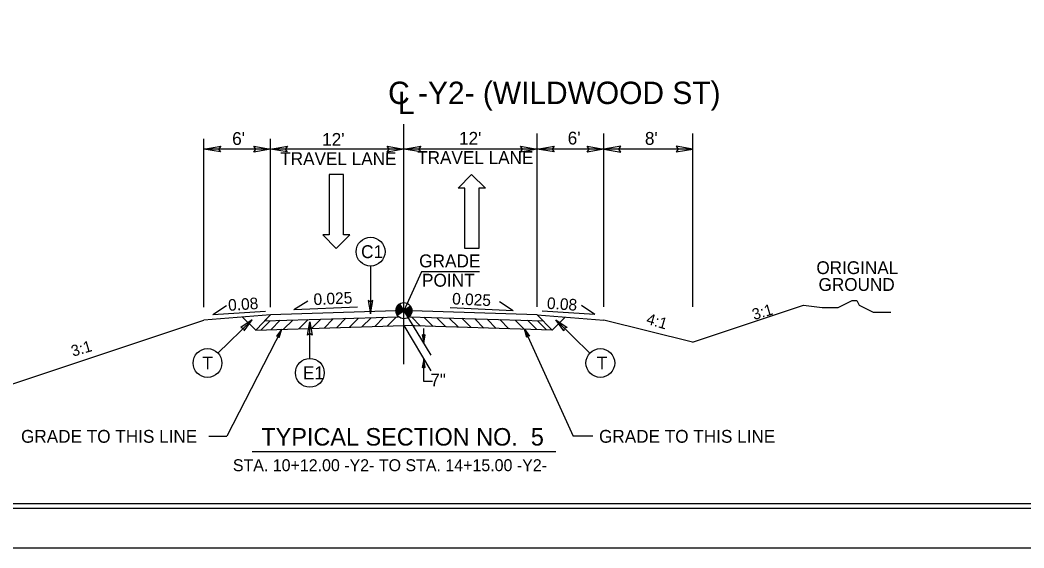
# Model space of a CAD drawing. Extents: x 2176156 to 2177167, y 76401 to 76644.
# Drawn here: x 2176675.5 to 2176765.8, y 76454.5 to 76502 of the extents above; entities that cross this region are included whole.
import ezdxf

# ---------------------------------------------------------------- set-up
doc = ezdxf.new("R2010")
doc.units = 0
for name, color, linetype in [('Exist Building', 7, 'Continuous'), ('Exist Building Metal Canopy', 7, 'Continuous'), ('Exist Roads Change in Surface', 7, 'Continuous'), ('Exist Roads Curbs', 7, 'Continuous'), ('Exist Roads EOP Other', 7, 'Continuous'), ('Exist Roads Soil', 7, 'Continuous'), ('Exist Structure Minor Culvert Topo', 7, 'Continuous'), ('Exist Structure Minor Drop Inlet', 7, 'Continuous'), ('Exist Utilities Other Pole CELL', 7, 'Continuous'), ('Exist Vegetation Woods Line', 7, 'Continuous'), ('Model Boundary Lines Text', 7, 'Continuous'), ('Old_Level_1', 7, 'Continuous'), ('Old_Level_3', 7, 'Continuous'), ('Prop North Arrow NAD83 for Plan Sheets CELL', 7, 'Continuous'), ('Sheet Cutting Line CELL', 7, 'Continuous'), ('Sheet Data Field CELL', 7, 'Continuous'), ('Sheet Plot Border Outside CELL', 7, 'Continuous'), ('Sheet Sticker Exception Certification CELL', 7, 'Continuous')]:
    doc.layers.add(name, color=color, linetype=linetype)

msp = doc.modelspace()

# ---------------------------------------------------------------- linework, layer by layer
at = {"layer": 'Exist Building'}
for p, q in [((2176696.696, 76474.077), (2176695.524, 76475.25)), ((2176723.371, 76474.077), (2176724.544, 76475.25)), ((2176696.696, 76474.077), (2176710.034, 76474.493)), ((2176723.371, 76474.077), (2176710.034, 76474.493))]:
    msp.add_line(p, q, dxfattribs=at)
at = {"layer": 'Exist Roads Change in Surface'}
for p, q in [((2176709.622, 76476.417), (2176710.034, 76475.825)), ((2176709.441, 76475.415), (2176710.034, 76475.825)), ((2176710.034, 76475.825), (2176709.441, 76475.415)), ((2176710.034, 76475.825), (2176710.625, 76476.237)), ((2176710.445, 76475.233), (2176710.034, 76475.825))]:
    msp.add_line(p, q, dxfattribs=at)
for points in [[(2176709.665, 76476.355), (2176709.401, 76476.171)], [(2176709.657, 76476.367), (2176709.417, 76476.2)], [(2176709.648, 76476.379), (2176709.437, 76476.231)], [(2176709.64, 76476.39), (2176709.464, 76476.268)], [(2176709.632, 76476.402), (2176709.498, 76476.309)], [(2176709.624, 76476.414), (2176709.559, 76476.369)], [(2176709.788, 76476.177), (2176709.313, 76475.846)], [(2176709.797, 76476.166), (2176709.313, 76475.829)], [(2176709.805, 76476.154), (2176709.313, 76475.812)], [(2176709.78, 76476.189), (2176709.314, 76475.864)], [(2176709.813, 76476.142), (2176709.314, 76475.794)], [(2176709.821, 76476.13), (2176709.314, 76475.777)], [(2176709.772, 76476.201), (2176709.315, 76475.883)], [(2176709.83, 76476.118), (2176709.316, 76475.76)], [(2176709.764, 76476.213), (2176709.317, 76475.902)], [(2176709.838, 76476.106), (2176709.317, 76475.744)], [(2176709.756, 76476.225), (2176709.319, 76475.921)], [(2176709.846, 76476.095), (2176709.319, 76475.728)], [(2176709.747, 76476.237), (2176709.321, 76475.94)], [(2176709.854, 76476.083), (2176709.322, 76475.712)], [(2176709.739, 76476.248), (2176709.325, 76475.96)], [(2176709.863, 76476.071), (2176709.325, 76475.697)], [(2176709.871, 76476.059), (2176709.328, 76475.681)], [(2176709.731, 76476.26), (2176709.33, 76475.981)], [(2176709.879, 76476.047), (2176709.331, 76475.666)], [(2176709.887, 76476.035), (2176709.334, 76475.65)], [(2176709.723, 76476.272), (2176709.335, 76476.002)], [(2176709.896, 76476.024), (2176709.338, 76475.636)], [(2176709.714, 76476.284), (2176709.341, 76476.024)], [(2176709.904, 76476.012), (2176709.342, 76475.621)], [(2176709.706, 76476.296), (2176709.347, 76476.046)], [(2176709.912, 76476), (2176709.347, 76475.606)], [(2176709.92, 76475.988), (2176709.352, 76475.593)], [(2176709.698, 76476.308), (2176709.355, 76476.069)], [(2176709.928, 76475.976), (2176709.357, 76475.578)], [(2176709.937, 76475.964), (2176709.362, 76475.565)], [(2176709.69, 76476.319), (2176709.364, 76476.092)], [(2176709.945, 76475.953), (2176709.368, 76475.551)], [(2176709.953, 76475.941), (2176709.373, 76475.537)], [(2176709.681, 76476.331), (2176709.374, 76476.117)], [(2176709.961, 76475.929), (2176709.379, 76475.524)], [(2176709.97, 76475.917), (2176709.386, 76475.511)], [(2176709.673, 76476.343), (2176709.387, 76476.144)], [(2176709.978, 76475.905), (2176709.391, 76475.497)], [(2176709.986, 76475.893), (2176709.398, 76475.484)], [(2176709.994, 76475.882), (2176709.405, 76475.472)], [(2176710.003, 76475.87), (2176709.412, 76475.459)], [(2176710.011, 76475.858), (2176709.42, 76475.447)], [(2176710.019, 76475.846), (2176709.427, 76475.434)], [(2176710.027, 76475.834), (2176709.436, 76475.422), (2176709.436, 76475.422)], [(2176710.629, 76476.231), (2176710.629, 76476.231), (2176710.037, 76475.82)], [(2176710.637, 76476.22), (2176710.046, 76475.808)], [(2176710.644, 76476.207), (2176710.054, 76475.796)], [(2176710.652, 76476.195), (2176710.062, 76475.784)], [(2176710.659, 76476.182), (2176710.07, 76475.772)], [(2176710.666, 76476.17), (2176710.079, 76475.761)], [(2176710.673, 76476.157), (2176710.087, 76475.749)], [(2176710.68, 76476.144), (2176710.095, 76475.737)], [(2176710.687, 76476.131), (2176710.103, 76475.725)], [(2176710.693, 76476.118), (2176710.111, 76475.713)], [(2176710.698, 76476.104), (2176710.12, 76475.701)], [(2176710.704, 76476.09), (2176710.128, 76475.69)], [(2176710.709, 76476.077), (2176710.136, 76475.678)], [(2176710.714, 76476.062), (2176710.144, 76475.666)], [(2176710.719, 76476.048), (2176710.153, 76475.654)], [(2176710.724, 76476.034), (2176710.161, 76475.642)], [(2176710.728, 76476.019), (2176710.169, 76475.63)], [(2176710.732, 76476.005), (2176710.177, 76475.619)], [(2176710.735, 76475.989), (2176710.186, 76475.607)], [(2176710.738, 76475.974), (2176710.194, 76475.595)], [(2176710.741, 76475.958), (2176710.202, 76475.583)], [(2176710.744, 76475.943), (2176710.21, 76475.571)], [(2176710.747, 76475.927), (2176710.219, 76475.559)], [(2176710.749, 76475.911), (2176710.227, 76475.548)], [(2176710.75, 76475.894), (2176710.235, 76475.536)], [(2176710.752, 76475.878), (2176710.243, 76475.524)], [(2176710.754, 76475.862), (2176710.251, 76475.512)], [(2176710.754, 76475.844), (2176710.26, 76475.5)], [(2176710.754, 76475.827), (2176710.268, 76475.488)], [(2176710.753, 76475.809), (2176710.276, 76475.477)], [(2176710.754, 76475.791), (2176710.284, 76475.465)], [(2176710.753, 76475.773), (2176710.293, 76475.453)], [(2176710.751, 76475.754), (2176710.301, 76475.441)], [(2176710.748, 76475.735), (2176710.309, 76475.429)], [(2176710.746, 76475.716), (2176710.317, 76475.417)], [(2176710.742, 76475.696), (2176710.326, 76475.406)], [(2176710.739, 76475.676), (2176710.334, 76475.394)], [(2176710.734, 76475.655), (2176710.342, 76475.382)], [(2176710.728, 76475.633), (2176710.35, 76475.37)], [(2176710.721, 76475.611), (2176710.359, 76475.358)], [(2176710.714, 76475.588), (2176710.367, 76475.346)], [(2176710.705, 76475.564), (2176710.375, 76475.335)], [(2176710.695, 76475.54), (2176710.383, 76475.323)], [(2176710.683, 76475.514), (2176710.391, 76475.311)], [(2176710.671, 76475.488), (2176710.4, 76475.299)], [(2176710.654, 76475.458), (2176710.408, 76475.287)], [(2176710.634, 76475.427), (2176710.416, 76475.275)], [(2176710.61, 76475.393), (2176710.424, 76475.264)], [(2176710.577, 76475.352), (2176710.433, 76475.252)], [(2176710.525, 76475.298), (2176710.441, 76475.24)]]:
    msp.add_lwpolyline(points, dxfattribs=at)
msp.add_circle((2176710.033, 76475.826), 0.721, dxfattribs=at)
for start, end in [(124.8249, 214.8249), (304.8249, 34.8249)]:
    msp.add_arc((2176710.033, 76475.826), 0.721, start, end, dxfattribs=at)
at = {"layer": 'Exist Roads Curbs'}
for p, q in [((2176709.314, 76475.777), (2176709.314, 76475.777)), ((2176709.319, 76475.728), (2176709.319, 76475.728)), ((2176709.334, 76475.65), (2176709.334, 76475.651)), ((2176709.338, 76475.636), (2176709.338, 76475.636)), ((2176709.347, 76475.606), (2176709.347, 76475.607)), ((2176709.379, 76475.524), (2176709.379, 76475.524)), ((2176709.391, 76475.497), (2176709.392, 76475.497)), ((2176709.398, 76475.484), (2176709.398, 76475.484)), ((2176709.405, 76475.472), (2176709.405, 76475.472)), ((2176709.412, 76475.459), (2176709.413, 76475.459)), ((2176697.504, 76474.907), (2176709.559, 76475.283)), ((2176709.427, 76475.434), (2176709.428, 76475.435)), ((2176709.436, 76475.422), (2176709.436, 76475.423)), ((2176709.442, 76475.414), (2176709.441, 76475.415)), ((2176709.441, 76475.415), (2176709.441, 76475.415)), ((2176710.508, 76475.283), (2176722.563, 76474.907))]:
    msp.add_line(p, q, dxfattribs=at)
for points in [[(2176745.986, 76476.316), (2176747.656, 76476.108), (2176748.074, 76476.108), (2176748.701, 76476.108), (2176749.119, 76476.108), (2176749.537, 76476.316), (2176749.954, 76476.526), (2176750.372, 76476.735), (2176750.789, 76476.735), (2176750.999, 76476.316), (2176751.417, 76476.108), (2176751.834, 76475.898), (2176752.252, 76475.69), (2176752.67, 76475.69), (2176753.087, 76475.69), (2176753.505, 76475.69), (2176753.844, 76475.69)], [(2176709.313, 76475.803), (2176698.034, 76475.451), (2176697.504, 76474.907), (2176709.559, 76475.283)], [(2176709.314, 76475.777), (2176709.314, 76475.777)], [(2176709.319, 76475.728), (2176709.319, 76475.728)], [(2176709.334, 76475.65), (2176709.334, 76475.65)], [(2176709.338, 76475.636), (2176709.338, 76475.636)], [(2176709.347, 76475.606), (2176709.347, 76475.606)], [(2176709.379, 76475.524), (2176709.379, 76475.524)], [(2176709.392, 76475.497), (2176709.391, 76475.497)], [(2176709.398, 76475.484), (2176709.398, 76475.484)], [(2176709.405, 76475.472), (2176709.405, 76475.472)], [(2176709.413, 76475.459), (2176709.412, 76475.459)], [(2176709.428, 76475.435), (2176709.427, 76475.434)], [(2176709.436, 76475.423), (2176709.436, 76475.422)]]:
    msp.add_lwpolyline(points, dxfattribs=at)
for start, end in [(181.84514, 183.8761), (183.88947, 185.20212), (185.20212, 186.51209), (186.51209, 187.80941), (187.82447, 189.07674), (189.07674, 192.8361), (192.8361, 194.07544), (194.0907, 195.29679), (195.29757, 196.50552), (196.50552, 197.7127), (197.71542, 198.88738), (198.88738, 200.09456), (200.09456, 204.78781), (204.78812, 207.10899), (207.11211, 208.26457), (208.26527, 209.41748), (209.41864, 210.56818), (210.57179, 211.71579), (211.71579, 212.8649), (212.86663, 214.01184), (214.01216, 214.77186), (214.8249, 228.84508)]:
    msp.add_arc((2176710.033, 76475.826), 0.721, start, end, dxfattribs=at)
at = {"layer": 'Exist Roads EOP Other'}
for p, q in [((2176698.034, 76475.451), (2176692.034, 76474.971)), ((2176710.654, 76475.458), (2176710.653, 76475.458)), ((2176710.671, 76475.488), (2176710.67, 76475.487)), ((2176710.683, 76475.514), (2176710.683, 76475.514)), ((2176710.714, 76475.588), (2176710.714, 76475.588)), ((2176710.721, 76475.611), (2176710.721, 76475.611)), ((2176710.734, 76475.655), (2176710.734, 76475.654)), ((2176710.739, 76475.676), (2176710.738, 76475.675)), ((2176710.742, 76475.696), (2176710.742, 76475.696)), ((2176710.746, 76475.716), (2176710.746, 76475.716)), ((2176710.753, 76475.773), (2176710.752, 76475.773)), ((2176710.754, 76475.791), (2176710.753, 76475.791)), ((2176722.034, 76475.451), (2176728.034, 76474.971)), ((2176735.986, 76472.983), (2176745.986, 76476.316)), ((2176673.75, 76468.876), (2176692.034, 76474.971)), ((2176710.525, 76475.298), (2176710.524, 76475.298)), ((2176710.577, 76475.352), (2176710.577, 76475.352)), ((2176710.61, 76475.393), (2176710.609, 76475.392)), ((2176710.634, 76475.427), (2176710.634, 76475.427)), ((2176735.986, 76472.983), (2176728.034, 76474.971))]:
    msp.add_line(p, q, dxfattribs=at)
for points in [[(2176710.508, 76475.283), (2176722.563, 76474.907), (2176722.034, 76475.451), (2176710.754, 76475.803)], [(2176710.654, 76475.458), (2176710.654, 76475.458)], [(2176710.67, 76475.488), (2176710.671, 76475.488)], [(2176710.683, 76475.514), (2176710.683, 76475.514)], [(2176710.714, 76475.588), (2176710.714, 76475.588)], [(2176710.721, 76475.611), (2176710.721, 76475.611)], [(2176710.734, 76475.655), (2176710.734, 76475.655)], [(2176710.738, 76475.676), (2176710.739, 76475.676)], [(2176710.742, 76475.696), (2176710.742, 76475.696)], [(2176710.746, 76475.716), (2176710.746, 76475.716)], [(2176710.752, 76475.773), (2176710.753, 76475.773)], [(2176710.753, 76475.791), (2176710.754, 76475.791)], [(2176710.525, 76475.299), (2176710.525, 76475.298)], [(2176710.577, 76475.353), (2176710.577, 76475.352)], [(2176710.61, 76475.393), (2176710.61, 76475.393)], [(2176710.634, 76475.428), (2176710.634, 76475.427)]]:
    msp.add_lwpolyline(points, dxfattribs=at)
for start, end in [(326.45695, 329.32655), (329.36485, 331.96034), (332.04132, 334.37636), (334.38027, 340.73102), (340.73681, 342.64285), (342.64598, 344.4557), (344.4557, 346.24045), (346.26481, 347.94552), (347.9775, 349.59802), (349.59837, 351.20379), (351.21961, 354.28369), (354.28369, 355.7778), (355.81267, 357.23939), (357.26518, 358.16121), (311.15703, 312.91767), (312.99666, 318.89175), (318.962, 323.02167), (323.07123, 326.39495)]:
    msp.add_arc((2176710.033, 76475.826), 0.721, start, end, dxfattribs=at)
at = {"layer": 'Exist Roads Soil'}
for p, q in [((2176698.034, 76475.451), (2176696.696, 76474.077)), ((2176722.034, 76475.451), (2176723.371, 76474.077))]:
    msp.add_line(p, q, dxfattribs=at)
at = {"layer": 'Exist Structure Minor Drop Inlet'}
for p, q in [((2176703.309, 76488.083), (2176703.309, 76482.651)), ((2176704.589, 76488.083), (2176703.309, 76488.083)), ((2176704.589, 76482.651), (2176704.589, 76488.083)), ((2176714.919, 76486.86), (2176716.122, 76488.083)), ((2176716.122, 76488.083), (2176717.364, 76486.86)), ((2176715.501, 76486.86), (2176714.919, 76486.86)), ((2176715.501, 76481.428), (2176715.501, 76486.86)), ((2176717.364, 76486.86), (2176716.782, 76486.86)), ((2176716.782, 76486.86), (2176716.782, 76481.428)), ((2176703.309, 76482.651), (2176702.727, 76482.651)), ((2176702.727, 76482.651), (2176703.929, 76481.428)), ((2176703.929, 76481.428), (2176705.171, 76482.651)), ((2176705.171, 76482.651), (2176704.589, 76482.651)), ((2176716.782, 76481.428), (2176715.501, 76481.428))]:
    msp.add_line(p, q, dxfattribs=at)
at = {"layer": 'Exist Utilities Other Pole CELL'}
for p, q in [((2176700.14, 76475.918), (2176701.38, 76476.713)), ((2176719.869, 76475.816), (2176718.629, 76476.611)), ((2176692.841, 76475.474), (2176694.066, 76476.294)), ((2176692.841, 76475.474), (2176697.587, 76475.788)), ((2176700.14, 76475.918), (2176705.85, 76476.184)), ((2176719.869, 76475.816), (2176714.207, 76476.079)), ((2176727.226, 76475.474), (2176722.48, 76475.788)), ((2176727.226, 76475.474), (2176726.002, 76476.294))]:
    msp.add_line(p, q, dxfattribs=at)
at = {"layer": 'Model Boundary Lines Text'}
for p, q in [((2176697.192, 76474.098), (2176698.006, 76474.922)), ((2176698.085, 76474.131), (2176698.907, 76474.963)), ((2176699.204, 76474.153), (2176700.026, 76474.985)), ((2176700.587, 76474.194), (2176701.409, 76475.026)), ((2176701.724, 76474.235), (2176702.548, 76475.069)), ((2176702.843, 76474.256), (2176703.666, 76475.088)), ((2176703.993, 76474.302), (2176704.818, 76475.137)), ((2176705.132, 76474.335), (2176705.952, 76475.164)), ((2176706.255, 76474.361), (2176707.077, 76475.193)), ((2176707.405, 76474.412), (2176708.229, 76475.246)), ((2176708.53, 76474.44), (2176709.357, 76475.277)), ((2176711.538, 76474.44), (2176710.711, 76475.277)), ((2176712.663, 76474.412), (2176711.838, 76475.246)), ((2176713.812, 76474.361), (2176712.99, 76475.193)), ((2176714.935, 76474.335), (2176714.116, 76475.164)), ((2176716.075, 76474.302), (2176715.249, 76475.137)), ((2176717.224, 76474.256), (2176716.402, 76475.088)), ((2176718.343, 76474.235), (2176717.519, 76475.069)), ((2176719.481, 76474.194), (2176718.659, 76475.026)), ((2176720.863, 76474.153), (2176720.041, 76474.985)), ((2176721.982, 76474.131), (2176721.16, 76474.963)), ((2176722.875, 76474.098), (2176722.062, 76474.922)), ((2176696.373, 76463.157), (2176723.694, 76463.157))]:
    msp.add_line(p, q, dxfattribs=at)
at = {"layer": 'Old_Level_1'}
for points in [[(2176693.543, 76490.111), (2176692.034, 76490.371), (2176693.552, 76490.64), (2176693.359, 76490.371)], [(2176696.524, 76490.631), (2176698.034, 76490.371), (2176696.516, 76490.103), (2176696.709, 76490.371)], [(2176699.543, 76490.111), (2176698.034, 76490.371), (2176699.552, 76490.64), (2176699.359, 76490.371)], [(2176708.524, 76490.631), (2176710.034, 76490.371), (2176708.516, 76490.103), (2176708.709, 76490.371)], [(2176711.543, 76490.111), (2176710.034, 76490.371), (2176711.552, 76490.64), (2176711.359, 76490.371)], [(2176720.524, 76490.631), (2176722.034, 76490.371), (2176720.516, 76490.103), (2176720.709, 76490.371)], [(2176723.543, 76490.111), (2176722.034, 76490.371), (2176723.552, 76490.64), (2176723.359, 76490.371)], [(2176726.524, 76490.631), (2176728.034, 76490.371), (2176726.516, 76490.103), (2176726.709, 76490.371)], [(2176729.543, 76490.631), (2176728.034, 76490.371), (2176729.552, 76490.103), (2176729.359, 76490.371)], [(2176734.524, 76490.111), (2176736.034, 76490.371), (2176734.516, 76490.64), (2176734.709, 76490.371)], [(2176698.816, 76473.42), (2176699.046, 76474.15), (2176698.579, 76473.537), (2176698.743, 76473.561)], [(2176711.69, 76473.647), (2176711.822, 76472.892), (2176711.954, 76473.652), (2176711.82, 76473.555)], [(2176721.084, 76473.414), (2176720.89, 76474.154), (2176721.326, 76473.519), (2176721.164, 76473.551)], [(2176711.954, 76470.719), (2176711.822, 76471.474), (2176711.69, 76470.714), (2176711.824, 76470.811)]]:
    msp.add_lwpolyline(points, close=True, dxfattribs=at)
at = {"layer": 'Old_Level_3'}
for p, q in [((2176710.034, 76487.808), (2176710.034, 76492.611)), ((2176722.034, 76476.183), (2176722.034, 76491.767)), ((2176728.034, 76476.183), (2176728.034, 76491.767)), ((2176736.034, 76476.183), (2176736.034, 76491.767)), ((2176692.034, 76476.139), (2176692.034, 76491.299)), ((2176698.034, 76476.139), (2176698.034, 76491.299)), ((2176698.034, 76490.371), (2176692.034, 76490.371)), ((2176710.034, 76490.371), (2176698.14, 76490.371)), ((2176722.034, 76490.371), (2176710.034, 76490.371)), ((2176736.034, 76490.371), (2176722.034, 76490.371)), ((2176710.034, 76471.005), (2176710.034, 76487.808)), ((2176710.034, 76475.825), (2176712.459, 76471.817)), ((2176699.046, 76474.15), (2176694.101, 76464.544)), ((2176710.034, 76474.493), (2176712.459, 76470.398)), ((2176711.822, 76472.892), (2176711.822, 76474.221)), ((2176720.89, 76474.154), (2176725.262, 76464.544)), ((2176711.822, 76469.46), (2176711.822, 76471.474)), ((2176712.602, 76469.46), (2176711.822, 76469.46)), ((2176692.475, 76464.544), (2176694.101, 76464.544)), ((2176727.029, 76464.544), (2176725.262, 76464.544))]:
    msp.add_line(p, q, dxfattribs=at)
at = {"layer": 'Prop North Arrow NAD83 for Plan Sheets CELL'}
for p, q in [((2176707.036, 76479.838), (2176707.036, 76475.536)), ((2176711.627, 76479.319), (2176710.034, 76475.825)), ((2176716.846, 76479.319), (2176711.627, 76479.319)), ((2176693.291, 76472.016), (2176696.37, 76474.996)), ((2176701.571, 76471.529), (2176701.571, 76474.825)), ((2176726.777, 76472.016), (2176723.697, 76474.996))]:
    msp.add_line(p, q, dxfattribs=at)
for points in [[(2176706.829, 76476.736), (2176707.036, 76475.536), (2176707.249, 76476.742), (2176707.036, 76476.589)], [(2176695.652, 76474.013), (2176696.37, 76474.996), (2176695.355, 76474.31), (2176695.613, 76474.263)], [(2176701.364, 76473.625), (2176701.571, 76474.825), (2176701.784, 76473.618), (2176701.571, 76473.772)], [(2176724.416, 76474.013), (2176723.697, 76474.996), (2176724.712, 76474.31), (2176724.454, 76474.263)]]:
    msp.add_lwpolyline(points, close=True, dxfattribs=at)
for centre in [(2176707.036, 76481.134), (2176692.359, 76471.114), (2176727.708, 76471.114), (2176701.571, 76470.233)]:
    msp.add_circle(centre, 1.296, dxfattribs=at)
at = {"layer": 'Sheet Cutting Line CELL'}
msp.add_lwpolyline([(2176898.707, 76630.475), (2176629.267, 76630.475), (2176629.267, 76454.475), (2176898.707, 76454.475)], close=True, dxfattribs=at)
at = {"layer": 'Sheet Data Field CELL'}
msp.add_lwpolyline([(2176895.987, 76626.475), (2176655.987, 76626.475), (2176655.987, 76458.475), (2176895.987, 76458.475)], close=True, dxfattribs=at)
at = {"layer": 'Sheet Plot Border Outside CELL'}
msp.add_lwpolyline([(2176897.987, 76626.883), (2176631.347, 76626.883), (2176631.347, 76458.067), (2176897.987, 76458.067)], close=True, dxfattribs=at)
at = {"layer": 'Sheet Sticker Exception Certification CELL'}
msp.add_line((2176629.267, 76454.475), (2176898.707, 76454.475), dxfattribs=at)

# ---------------------------------------------------------------- texts
at = {"layer": 'Exist Building Metal Canopy'}
msp.add_text('TYPICAL SECTION NO.  5', height=1.5766, rotation=0.00002, dxfattribs=at).set_placement((2176697.206, 76463.685))
at = {"layer": 'Exist Roads Curbs'}
for s, rotation, p in [('3:1', 16.46494, (2176741.532, 76474.971)), ('4:1', 343.53506, (2176731.771, 76474.659)), ('3:1', 16.46494, (2176680.257, 76471.677))]:
    msp.add_text(s, height=1.0064, rotation=rotation, dxfattribs=at).set_placement(p)
at = {"layer": 'Exist Structure Minor Culvert Topo'}
for s, height, p in [("6'", 1.1533, (2176694.579, 76490.739)), ("12'", 1.1533, (2176702.678, 76490.66)), ("12'", 1.1533, (2176714.996, 76490.761)), ("6'", 1.1533, (2176724.773, 76490.78)), ("8'", 1.1533, (2176731.72, 76490.752)), ('TRAVEL LANE', 1.15334, (2176698.908, 76488.93)), ('TRAVEL LANE', 1.15334, (2176711.226, 76489.031)), ('ORIGINAL', 1.1533, (2176747.146, 76479.118)), ('GROUND', 1.1533, (2176747.34, 76477.606)), ('GRADE TO THIS LINE', 1.15334, (2176675.583, 76463.94)), ('GRADE TO THIS LINE', 1.15334, (2176727.592, 76463.94))]:
    msp.add_text(s, height=height, dxfattribs=at).set_placement(p)
at = {"layer": 'Exist Utilities Other Pole CELL'}
for s, rotation, p in [('0.025', 2.6676, (2176701.926, 76476.323)), ('0.025 ', 357.3324, (2176714.355, 76476.395)), ('0.08', 3.78012, (2176694.251, 76475.804)), ('0.08', 356.21988, (2176722.876, 76475.998))]:
    msp.add_text(s, height=1.0429, rotation=rotation, dxfattribs=at).set_placement(p)
at = {"layer": 'Exist Vegetation Woods Line'}
for s, height, p in [('C -Y2- (WILDWOOD ST)', 2.01314, (2176708.613, 76494.422)), ('STA. 10+12.00 -Y2- TO STA. 14+15.00 -Y2-', 1.0742, (2176694.643, 76461.382))]:
    msp.add_text(s, height=height, dxfattribs=at).set_placement(p)
msp.add_text('L', height=2.013, rotation=359.9469, dxfattribs=at).set_placement((2176709.491, 76493.52))
at = {"layer": 'Prop North Arrow NAD83 for Plan Sheets CELL'}
for s, rotation, p in [('C1', 359.99974, (2176706.179, 76480.554)), ('GRADE', 0.00015, (2176711.405, 76479.724)), ('POINT', 0.00015, (2176711.658, 76477.984)), ('T', 359.99974, (2176691.902, 76470.534)), ('T', 0.00026, (2176727.381, 76470.534)), ('E1', 0.00026, (2176700.943, 76469.653))]:
    msp.add_text(s, height=1.16, rotation=rotation, dxfattribs=at).set_placement(p)
msp.add_text('7"', height=1.1533, dxfattribs=at).set_placement((2176712.407, 76469.011))

doc.saveas('drawing.dxf')
